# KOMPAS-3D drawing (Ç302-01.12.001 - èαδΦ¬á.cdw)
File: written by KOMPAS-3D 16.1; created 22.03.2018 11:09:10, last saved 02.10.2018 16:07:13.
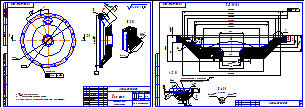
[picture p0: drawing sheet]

Sheets 1-2: A3, landscape

Title block, sheet 1: name: Крышка; designation: А302-01.12.001; mass: 1,64; scale: 1:2; sheet number: 1; sheets: 2; organisation: ЗАО «Астерион»; sheet format: A3; stored path: Z:\Мембранные насосы\Мембранный электропривод\А302-00.00.000 - ASTRA-302 (МЭ200)\Чертежи\А302-00.12.001 - Крышка.cdw; drawn by: Милов; technical control: Лучихин
Title block, sheet 2: sheet number: 2

Views: Вид 1, Вид:4, Проекционный вид 2, Местный разрез 1, Разрез А-А, Выносной элемент 4, Выносной элемент 5, Выносной элемент 7, Выносной элемент Б, Выносной элемент, Выносной элемент В, Вид:1, Вид:2, Вид:3
Referenced files in Z:\Мембранные насосы\Мембранный электропривод\А302-00.00.000 - ASTRA-302 (МЭ200)\3Д\: А302-00.12.001 - Крышка.m3d
Referenced files in \\192.168.87.28\Konstructor_doc\Мембранные насосы\Мембранный электропривод\А302-00.00.000 - ASTRA-302 (МЭ200)\3Д ПВХ\: А302-01.12.001 - Крышка.m3d
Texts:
  Стержень ПВХ
  цвет серый
  Зона контакта с мембраной
  поверхность глянцевая
  *Размеры для справок.
  ** Обеспечить инструментом.
  Общие допуски ГОСТ 30893.2-mK (H14, h14,  t2/2).
  Ra 3,2
  Ra 3,2 ( )
Dimensions and other numbers on the sheet: 302; 287; 12 отв.; 6,5; 50,2; 280; 36; 0,8; 46; 270±0,4; 16,95; 24,53; 244±0,2; 206; 202; 155,43; 68; 6; 0,5; 258±0,3; 0,1; 33; 178; 65; 44; 28; 8; 73; 54; 1±0,1; 2; 12,5; 12; 2 места; 1:2; 1,64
